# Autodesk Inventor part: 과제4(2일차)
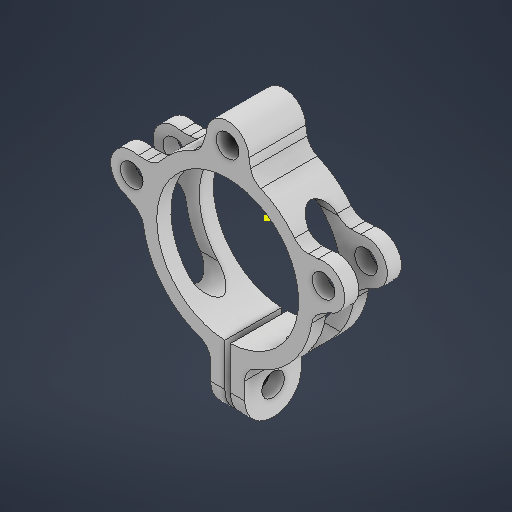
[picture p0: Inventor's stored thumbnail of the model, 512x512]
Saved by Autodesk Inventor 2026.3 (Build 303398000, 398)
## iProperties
Created: 2026-08
Part Number: 과제4(2일차)
Material: 일반
Document SubType Name: Modeling
Designer: chang
Density: 1 g/cm^3
Appearance: 기본값
Author: chang
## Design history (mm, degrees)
sketch "스케치3"
  geometry: L1 (0, 0)-(33.807, 9.059); L2 (0, 0)-(35, 0); L3 (0, 0)-(0, 35); L4 (0, 0)-(-33.807, 9.059); L5 (0, 0)-(35, 0); L6 (-7.5, 35)-(-8.857, 31.004); L7 (7.5, 35)-(8.095, 32.005); L8 (31.866, 16.303)-(28.531, 16.199); L9 (35.749, 1.814)-(32.442, -0.235); L10 (-35.749, 1.814)-(-32.625, 0.011); L11 (-31.512, 16.199)-(-28.341, 16.199); L12 (45.377, 0.011)-(95.377, 0.011); L13 (-6, -79.922)-(6, -79.922); L14 (-6, -49.989)-(-6, -39.989); L15 (6, -49.989)-(6, -39.989); L16 (6, -39.989)-(6, -33.941); L17 (-6, -39.989)-(-6, -33.941); L18 (-6, -49.989)-(-1, -49.989); L19 (6, -49.989)-(1, -49.989); L20 (1, -49.989)-(1, -24.98); L21 (-1, -49.989)-(-1, -24.98); C1 r 4 at (-33.807, 9.059); C2 r 4 at (0, 35); C3 r 4 at (33.807, 9.059); A1 r 25 centre (0, 0) between (1, -24.98) and (-1, -24.98); A2 r 7.5 centre (0, 35) between (7.5, 35) and (-7.5, 35); A3 r 7.5 centre (-33.807, 9.059) between (-31.512, 16.199) and (-35.749, 1.814); A4 r 7.5 centre (33.807, 9.059) between (35.749, 1.814) and (31.866, 16.303); A5 r 6 centre (-14.538, 32.934) between (-12.115, 27.445) and (-8.857, 31.004); A6 r 6 centre (13.98, 33.175) between (8.095, 32.005) and (11.65, 27.646); A7 r 30 centre (0, 0) between (23.619, 18.497) and (11.65, 27.646); A8 r 6 centre (28.343, 22.196) between (23.619, 18.497) and (28.531, 16.199); A9 r 6 centre (35.602, -5.335) between (32.442, -0.235) and (29.669, -4.446); A10 r 30 centre (0, 0) between (-12.115, 27.445) and (-23.617, 18.499); A11 r 6 centre (-35.625, -5.186) between (-29.687, -4.321) and (-32.625, 0.011); A12 r 6 centre (-28.341, 22.199) between (-28.341, 16.199) and (-23.617, 18.499); A13 r 30 centre (0, 0) between (-29.687, -4.321) and (-10, -28.284); A14 r 30 centre (0, 0) between (10, -28.284) and (29.669, -4.446); A15 r 6 centre (-12, -33.941) between (-6, -33.941) and (-10, -28.284); A16 r 6 centre (12, -33.941) between (10, -28.284) and (6, -33.941); 9 further points
  constraints: 42 end point, 36 point on circle, 20 tangent, 19 centre point, 9 point on line, 8 coincident, 6 horizontal, 4 equal radius, 2 equal length, 2 parallel, 2 perpendicular, 2 vertical
  dimensions: "d13" = 50 diameter of A1; "d14" = 35 distance of L1.start L1.end; "d15" = 15 deg angle of L2 L1; "d16" = 35 distance of L1.start L3.end; "d17" = 35 distance of L1.start L4.end; "d18" = 165 deg angle of L5 L4; "d19" = 8 diameter of C1; "d20" = 8 diameter of C2; "d21" = 8 diameter of C3; "d22" = 15 diameter of A2; "d23" = 15 diameter of A3; "d24" = 15 diameter of A4; "d26" = 30 deg angle of L7 L6; "d27" = 6 radius of A5 (derived); "d28" = 30 deg angle of L9 L8; "d29" = 6 radius of A8 (derived); "d30" = 30 deg angle of L11 L10; "d31" = 6 radius of A11 (derived); "d34" = 12 distance of L13.start L13.end; "d36" = 5 distance of L14.start L18.end; "d38" = 6 radius of A15 (derived); "d39" = 30 radius of A14; "d40" = 31.7893 deg angle of L12 L9; "d41" = 101.241 deg angle of L12 L7; "d42" = 0.01059 distance between parallel lines of L12 L5; "d43" = 50 distance between parallel lines of L12 L19; "d44" = 79.93233 distance between parallel lines of L12 L13; "d45" = 50 distance between parallel lines of L12 L18; "d46" = 16.18831 distance between parallel lines of L12 L11; "d47" = 5 distance between parallel lines of L20 L16; "d48" = 6 distance between parallel lines of L16 L3; "d49" = 7 distance between parallel lines of L21 L16; "d50" = 12 distance between parallel lines of L16 L17; "d51" = 17.29016 distance from line of point (0, 0) L9; "d52" = 15.30016 distance from line of point (0, 0) L8; "d53" = 14.17888 distance from line of point (0, 0) L7; "d54" = 18.35719 distance from line of point (0, 0) L6; "d55" = 16.30311 distance from line of point (0, 0) L10; "d56" = 32.94524 distance from line of L12.end L9; "d57" = 6.60538 distance from line of L12.start L9; "d58" = 1.79194 distance from line of point (29.947, -1.781) L12; "d59" = 28.68404 distance from line of point (8.753, 28.695) L12; "d60" = 40 distance from line of L15.end L12; "d61" = 53.80338 distance from line of L13.end L9; "d62" = 28.36034 distance from line of point (-9.751, 28.371) L12; "d63" = 1.53775 distance from line of point (-29.961, -1.527) L12
extrude "돌출1" new body sketch "스케치3" distance "d64" = 20; taper "d65" = 0 deg
fillet "모깎기1" dims "d66" = 10
fillet "모깎기2" dims "d67" = 10
fillet "모깎기3" dims "d68" = 10
fillet "모깎기4" dims "d69" = 10
sketch "스케치4"
  geometry: C1 r 4 at (10, -6.048); A1 r 10 centre (10, -6.048) between (0, -6.048) and (20, -6.048) reference; 1 further point
  constraints: 1 centre point, 1 coincident
  dimensions: "d70" = 8 diameter of C1
extrude "돌출2" cut sketch "스케치4" distance "d71" = 5; taper "d72" = 0 deg
sketch "스케치5"
  geometry: C1 r 4 at (10, -6.048); A1 r 10 centre (10, -6.048) between (0, -6.048) and (20, -6.048) reference; 1 further point
  constraints: 1 centre point, 1 coincident
  dimensions: "d73" = 8 diameter of C1
extrude "돌출3" cut sketch "스케치5" distance "d74" = 5; taper "d75" = 0 deg
sketch "스케치6"
  geometry: 1 further point
sketch "스케치7"
  geometry: 1 further point
sketch "스케치8"
  geometry: 1 further point
sketch "스케치9"
  geometry: L1 (5, 16.952)-(5, 51.952) reference; L2 (15, 51.952)-(15, 16.952); A1 r 5 centre (10, 16.952) between (5, 16.952) and (15, 16.952); A2 r 5 centre (10, 51.952) between (15, 51.952) and (5, 51.952); 1 further point
  constraints: 4 end point, 4 point on circle, 3 tangent, 2 centre point, 2 vertical, 2 other
  dimensions: "d76" = 10 diameter of A1; "d77" = 10 diameter of A2
extrude "돌출4" cut sketch "스케치9" distance "d78" = 36.5; taper "d80" = 0 deg; dims "d79" = 54.5, "d81" = 0
node "솔리드1"
